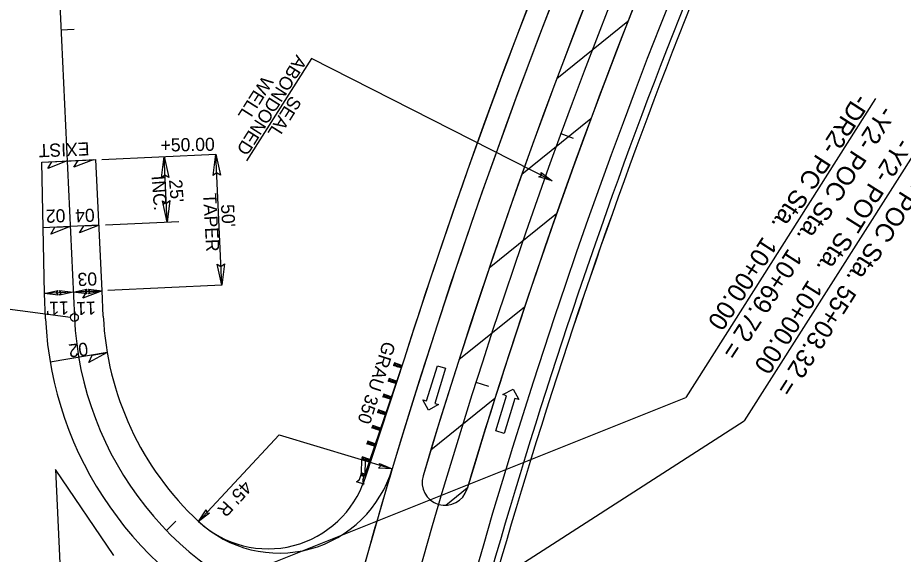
# Model space of a CAD drawing. Extents: x 1778969 to 1790720, y 807089 to 817794.
# Drawn here: x 1780913.9 to 1781249.7, y 812166.6 to 812371.1 of the extents above; entities that cross this region are included whole.
import ezdxf

# ---------------------------------------------------------------- set-up
doc = ezdxf.new("R2010")
doc.units = 0
for name, color, linetype in [('Prop CMT Guardrail Graphics', 7, 'Continuous'), ('Prop Conc Shoulder Berm Gutter', 7, 'Continuous'), ('Prop Dimension', 7, 'Continuous'), ('Prop Dimension Text', 7, 'Continuous'), ('Prop DSN Text', 7, 'Continuous'), ('Prop EOT', 7, 'Continuous'), ('Prop Guardrail', 7, 'Continuous'), ('Prop Guardrail Anchor Unit CELL', 7, 'Continuous'), ('Prop Hatching', 7, 'Continuous'), ('Prop Horizontal Alignment', 7, 'Continuous'), ('Prop Horizontal Alignment Station Label', 7, 'Continuous'), ('Prop Horizontal Alignment Tick Small', 7, 'Continuous'), ('Prop Lane Arrow CELL', 7, 'Continuous'), ('Prop Lane Lines', 7, 'Continuous'), ('Prop Paved Shoulder', 7, 'Continuous'), ('Prop Rem of Exist Asph Pvmt', 7, 'Continuous'), ('Prop Superelevation  Arrow CELL', 7, 'Continuous'), ('Prop Superelevation Label', 7, 'Continuous'), ('Prop Terminator CELL', 7, 'Continuous'), ('Scratch_Level_2', 7, 'Continuous'), ('Scratch_Level_3', 7, 'Continuous'), ('Scratch_Level_7', 7, 'Continuous')]:
    doc.layers.add(name, color=color, linetype=linetype)

msp = doc.modelspace()

# ---------------------------------------------------------------- linework, layer by layer
at = {"layer": 'Prop CMT Guardrail Graphics'}
msp.add_line((1781061.04, 812240.97), (1781045.25, 812192.86), dxfattribs=at)
msp.add_arc((1783308.81, 811525.98), 2358.75, 152.51849, 162.35467, dxfattribs=at)
at = {"layer": 'Prop Conc Shoulder Berm Gutter'}
msp.add_arc((1783308.81, 811525.98), 2303.58, 153.74801, 164.19896, dxfattribs=at)
at = {"layer": 'Prop Dimension'}
for p, q in [((1780945.89, 812317.07), (1780989.3, 812319.1)), ((1780970.82, 812293.21), (1780969.65, 812318.18)), ((1780991.63, 812269.15), (1780989.3, 812319.1)), ((1780947.3, 812292.11), (1780975.24, 812293.42)), ((1780935.02, 812266.51), (1780924.04, 812266)), ((1780946.01, 812267.03), (1780936.2, 812266.57)), ((1780991.63, 812269.15), (1780948.22, 812267.13)), ((1781013.41, 812212.1), (1780982.8, 812179.11)), ((1781013.41, 812212.1), (1781056.53, 812199.21))]:
    msp.add_line(p, q, dxfattribs=at)
at = {"layer": 'Prop DSN Text'}
for p, q in [((1781025.77, 812355.45), (1781001.08, 812316.55)), ((1781117.48, 812308.94), (1781025.77, 812355.45))]:
    msp.add_line(p, q, dxfattribs=at)
at = {"layer": 'Prop EOT'}
for p, q in [((1780923.03, 812316.01), (1780943.69, 812316.97)), ((1780946.01, 812267.03), (1780943.68, 812316.97)), ((1780924.04, 812266), (1780923.03, 812316.01)), ((1780946.46, 812257.37), (1780946.01, 812267.03)), ((1780924.49, 812256.35), (1780924.04, 812266))]:
    msp.add_line(p, q, dxfattribs=at)
for centre, radius, start, end in [((1783308.81, 811525.98), 2350.75, 144.08998, 163.35801), ((1783308.81, 811525.98), 2309.25, 153.74801, 174.52695), ((1781060.34, 812262.68), 114, 182.6702, 227.147), ((1781060.34, 812262.68), 136, 182.6702, 247.3077), ((1781013.41, 812212.1), 45, 227.147, 343.358)]:
    msp.add_arc(centre, radius, start, end, dxfattribs=at)
at = {"layer": 'Prop Guardrail'}
for radius, start, end in [(2358.75, 144.08998, 162.35467), (2301.25, 153.74801, 164.19128)]:
    msp.add_arc((1783308.81, 811525.98), radius, start, end, dxfattribs=at)
at = {"layer": 'Prop Guardrail Anchor Unit CELL'}
for p, q in [((1781061.04, 812240.97), (1781045.97, 812196.71)), ((1781057.38, 812239.53), (1781057.05, 812238.58)), ((1781057.05, 812238.58), (1781058.8, 812239.05)), ((1781059.89, 812237.62), (1781057.05, 812238.58)), ((1781060.22, 812238.56), (1781057.38, 812239.53)), ((1781058.47, 812238.1), (1781057.38, 812239.53)), ((1781058.8, 812239.05), (1781058.47, 812238.1)), ((1781058.47, 812238.1), (1781060.22, 812238.56)), ((1781059.89, 812237.62), (1781058.47, 812238.1)), ((1781058.8, 812239.05), (1781059.89, 812237.62)), ((1781060.22, 812238.56), (1781059.89, 812237.62)), ((1781055.3, 812233.58), (1781054.97, 812232.64)), ((1781054.97, 812232.64), (1781056.74, 812233.09)), ((1781058.19, 812232.6), (1781055.3, 812233.58)), ((1781056.42, 812232.14), (1781055.3, 812233.58)), ((1781056.74, 812233.09), (1781056.42, 812232.14)), ((1781056.74, 812233.09), (1781057.86, 812231.65)), ((1781057.86, 812231.65), (1781054.97, 812232.64)), ((1781058.19, 812232.6), (1781056.42, 812232.14)), ((1781053.27, 812227.62), (1781052.95, 812226.67)), ((1781052.95, 812226.67), (1781054.71, 812227.13)), ((1781055.83, 812225.69), (1781052.95, 812226.67)), ((1781056.15, 812226.63), (1781053.27, 812227.62)), ((1781054.39, 812226.18), (1781053.27, 812227.62)), ((1781054.71, 812227.13), (1781054.39, 812226.18)), ((1781056.15, 812226.63), (1781054.39, 812226.18)), ((1781054.71, 812227.13), (1781055.83, 812225.69)), ((1781051.25, 812221.65), (1781050.93, 812220.7)), ((1781050.93, 812220.7), (1781052.69, 812221.16)), ((1781053.8, 812219.72), (1781050.93, 812220.7)), ((1781054.12, 812220.67), (1781051.25, 812221.65)), ((1781052.36, 812220.21), (1781051.25, 812221.65)), ((1781052.69, 812221.16), (1781052.36, 812220.21)), ((1781054.12, 812220.67), (1781052.36, 812220.21)), ((1781052.69, 812221.16), (1781053.8, 812219.72)), ((1781054.12, 812220.67), (1781053.8, 812219.72)), ((1781049.12, 812215.72), (1781048.8, 812214.77)), ((1781048.8, 812214.77), (1781050.61, 812215.21)), ((1781051.77, 812213.76), (1781048.8, 812214.77)), ((1781052.09, 812214.7), (1781049.12, 812215.72)), ((1781050.29, 812214.26), (1781049.12, 812215.72)), ((1781050.61, 812215.21), (1781050.29, 812214.26)), ((1781052.09, 812214.7), (1781050.29, 812214.26)), ((1781050.61, 812215.21), (1781051.77, 812213.76)), ((1781047.22, 812209.71), (1781046.9, 812208.76)), ((1781050.06, 812208.74), (1781047.22, 812209.71)), ((1781048.32, 812208.28), (1781047.22, 812209.71)), ((1781046.9, 812208.76), (1781048.64, 812209.22)), ((1781049.74, 812207.79), (1781046.9, 812208.76)), ((1781048.64, 812209.22), (1781048.32, 812208.28)), ((1781050.06, 812208.74), (1781048.32, 812208.28)), ((1781048.64, 812209.22), (1781049.74, 812207.79)), ((1781044.81, 812202.81), (1781044.71, 812197.67)), ((1781045.13, 812203.76), (1781044.81, 812202.81)), ((1781044.81, 812202.81), (1781046.58, 812203.27)), ((1781047.71, 812201.83), (1781044.81, 812202.81)), ((1781048.03, 812202.77), (1781045.13, 812203.76)), ((1781046.26, 812202.32), (1781045.13, 812203.76)), ((1781046.58, 812203.27), (1781046.26, 812202.32)), ((1781048.03, 812202.77), (1781046.26, 812202.32)), ((1781046.58, 812203.27), (1781047.71, 812201.83)), ((1781046.26, 812202.32), (1781046.13, 812197.19)), ((1781044.1, 812195.13), (1781044.72, 812197.08)), ((1781044.71, 812197.67), (1781044.39, 812196.72)), ((1781044.39, 812196.72), (1781046.13, 812197.19)), ((1781045.81, 812196.24), (1781044.39, 812196.72)), ((1781044.71, 812197.67), (1781044.55, 812197.2)), ((1781046.13, 812197.19), (1781044.71, 812197.67)), ((1781045.81, 812196.24), (1781044.71, 812197.67)), ((1781044.72, 812197.08), (1781045.3, 812196.9)), ((1781045.89, 812196.71), (1781045.26, 812194.76)), ((1781045.3, 812196.9), (1781045.89, 812196.71)), ((1781042.92, 812194.27), (1781044.1, 812195.13)), ((1781045.72, 812193.38), (1781042.92, 812194.27)), ((1781045.26, 812194.76), (1781045.72, 812193.38))]:
    msp.add_line(p, q, dxfattribs=at)
at = {"layer": 'Prop Hatching'}
for p, q in [((1781146.27, 812369.55), (1781119.18, 812347.72)), ((1781132.19, 812332.52), (1781105.85, 812311.3)), ((1781119.1, 812296.29), (1781093.46, 812275.63)), ((1781106.94, 812260.81), (1781081.93, 812240.66)), ((1781095.63, 812226.01), (1781071.21, 812206.33)), ((1781085.12, 812191.86), (1781076.97, 812185.29))]:
    msp.add_line(p, q, dxfattribs=at)
at = {"layer": 'Prop Horizontal Alignment'}
msp.add_line((1780911.31, 812775.03), (1780935.47, 812256.86), dxfattribs=at)
for centre, radius, start, end in [((1783308.81, 811525.98), 2330, 144.08998, 185.35942), ((1781060.34, 812262.68), 125, 182.6702, 254.314)]:
    msp.add_arc(centre, radius, start, end, dxfattribs=at)
at = {"layer": 'Prop Horizontal Alignment Station Label'}
for p, q in [((1781240.65, 812340.23), (1781168.41, 812226.38)), ((1781257.48, 812322.83), (1781190.63, 812217.49)), ((1780933.98, 812256.79), (1780712.98, 812286.51)), ((1780995.43, 812157.24), (1781168.41, 812226.38)), ((1781060.57, 812133.95), (1781190.63, 812217.49))]:
    msp.add_line(p, q, dxfattribs=at)
msp.add_circle((1780935.47, 812256.86), 1.5, dxfattribs=at)
at = {"layer": 'Prop Horizontal Alignment Tick Small'}
for p, q in [((1780930.37, 812366.4), (1780935.36, 812366.64)), ((1781120.78, 812326.87), (1781125.48, 812325.15)), ((1780935.02, 812266.51), (1780940.02, 812266.75)), ((1781088.43, 812232.26), (1781093.2, 812230.74)), ((1780970.54, 812175.73), (1780974.13, 812179.21))]:
    msp.add_line(p, q, dxfattribs=at)
at = {"layer": 'Prop Lane Arrow CELL'}
for p, q in [((1781069.61, 812225.08), (1781073.71, 812238.47)), ((1781076.86, 812237.51), (1781072.77, 812224.12)), ((1781073.71, 812238.47), (1781076.86, 812237.51)), ((1781098.67, 812227.45), (1781102.56, 812229.56)), ((1781102.56, 812229.56), (1781104.7, 812225.61)), ((1781096.01, 812213.62), (1781100.11, 812227.01)), ((1781100.11, 812227.01), (1781098.67, 812227.45)), ((1781070.31, 812221.58), (1781068.18, 812225.52)), ((1781068.18, 812225.52), (1781069.61, 812225.08)), ((1781074.2, 812223.68), (1781070.31, 812221.58)), ((1781072.77, 812224.12), (1781074.2, 812223.68)), ((1781103.26, 812226.05), (1781099.16, 812212.66)), ((1781104.7, 812225.61), (1781103.26, 812226.05)), ((1781099.16, 812212.66), (1781096.01, 812213.62))]:
    msp.add_line(p, q, dxfattribs=at)
at = {"layer": 'Prop Lane Lines'}
for centre, radius, start, end in [((1783308.81, 811525.98), 2338.75, 144.36073, 163.33829), ((1783308.81, 811525.98), 2321.25, 144.3813, 163.33829), ((1783308.81, 811525.98), 2338.75, 148.12573, 163.33829), ((1783308.81, 811525.98), 2321.25, 148.12573, 163.33829), ((1783308.81, 811525.98), 2321.25, 153.74801, 163.33829), ((1781076.64, 812194.04), 8.75, 163.3383, 343.3383), ((1781076.64, 812194.04), 8.75, 163.3383, 343.3383)]:
    msp.add_arc(centre, radius, start, end, dxfattribs=at)
at = {"layer": 'Prop Paved Shoulder'}
msp.add_line((1781061.04, 812240.97), (1781046.1, 812195.43), dxfattribs=at)
for centre, radius, start, end in [((1783308.81, 811525.98), 2358.75, 144.08998, 162.35467), ((1781009.23, 812207.53), 38.8, 227.0833, 341.8379)]:
    msp.add_arc(centre, radius, start, end, dxfattribs=at)
at = {"layer": 'Prop Rem of Exist Asph Pvmt'}
msp.add_line((1780950.52, 812166.14), (1780928.32, 812198.92), dxfattribs=at)
msp.add_lwpolyline([(1780928.32, 812198.92), (1780930.56, 812149.53), (1780931.1, 812134.79), (1780931.23, 812131.33)], dxfattribs=at)
at = {"layer": 'Prop Superelevation  Arrow CELL'}
for p, q in [((1780923.03, 812316.01), (1780942.68, 812316.92)), ((1780933.86, 812291.49), (1780923.53, 812291)), ((1780944.85, 812292), (1780933.86, 812291.49)), ((1780935.02, 812266.51), (1780946.01, 812267.03)), ((1780947.97, 812243.48), (1780926.28, 812239.77))]:
    msp.add_line(p, q, dxfattribs=at)
for points in [[(1780942.68, 812316.92), (1780935.31, 812314.08), (1780936.91, 812316.66)], [(1780932.69, 812316.46), (1780925.32, 812313.61), (1780926.92, 812316.19)], [(1780933.86, 812291.49), (1780926.48, 812288.64), (1780928.08, 812291.22)], [(1780944.85, 812292), (1780937.47, 812289.15), (1780939.07, 812291.73)], [(1780946.01, 812267.03), (1780938.64, 812264.18), (1780940.24, 812266.76)], [(1780947.97, 812243.48), (1780941, 812239.75), (1780942.27, 812242.5)]]:
    msp.add_lwpolyline(points, close=True, dxfattribs=at)
at = {"layer": 'Prop Terminator CELL'}
for points in [[(1780968.64, 812310.03), (1780969.65, 812318.18), (1780971.47, 812310.11), (1780969.98, 812311.08)], [(1780988.29, 812310.94), (1780989.3, 812319.1), (1780991.12, 812311.03), (1780989.63, 812312)], [(1781113.26, 812312.08), (1781117.48, 812308.94), (1781112.42, 812310.47), (1781113.43, 812310.99)], [(1780971.83, 812301.37), (1780970.82, 812293.21), (1780969, 812301.28), (1780970.49, 812300.31)], [(1780992.65, 812277.31), (1780991.63, 812269.15), (1780989.81, 812277.22), (1780991.3, 812276.26)], [(1780929.26, 812265.35), (1780924.04, 812266), (1780929.2, 812267.16), (1780928.58, 812266.21)], [(1780929.8, 812267.16), (1780935.02, 812266.51), (1780929.86, 812265.35), (1780930.48, 812266.3)], [(1780940.24, 812265.86), (1780935.02, 812266.51), (1780940.19, 812267.68), (1780939.57, 812266.73)], [(1780940.79, 812267.68), (1780946.01, 812267.03), (1780940.85, 812265.86), (1780941.47, 812266.81)], [(1781051.68, 812201.25), (1781056.53, 812199.21), (1781051.24, 812199.49), (1781052.09, 812200.24)], [(1780986.98, 812182.3), (1780982.8, 812179.11), (1780985.67, 812183.56), (1780985.9, 812182.44)]]:
    msp.add_lwpolyline(points, close=True, dxfattribs=at)
at = {"layer": 'Scratch_Level_2'}
msp.add_arc((1783308.81, 811525.98), 2350.75, 163.35801, 165.95604, dxfattribs=at)
at = {"layer": 'Scratch_Level_3'}
msp.add_arc((1783308.81, 811525.98), 2350.75, 144.08998, 164.89021, dxfattribs=at)
at = {"layer": 'Scratch_Level_7'}
msp.add_arc((1783308.81, 811525.98), 2301.26, 153.74801, 164.19128, dxfattribs=at)

# ---------------------------------------------------------------- texts
at = {"layer": 'Prop Dimension Text'}
for s, rotation, p in [('+50.00', 0.9523, (1780968.34, 812320.02)), ('INC.', 274.341, (1780964.81, 812310.71)), ("25'", 274.341, (1780971.5, 812309.26)), ('TAPER', 273.1477, (1780984.5, 812304.03)), ("50'", 273.1477, (1780991.29, 812299.87)), ("11'", 181.4489, (1780933.31, 812263.01)), ("11'", 182.1397, (1780943.58, 812262.98)), ("45' R", 227.1014, (1780999.99, 812195.09))]:
    msp.add_text(s, height=5, rotation=rotation, dxfattribs=at).set_placement(p)
at = {"layer": 'Prop DSN Text'}
for s, p in [('ABONDONED', (1781020.11, 812357.16)), ('WELL', (1781007.32, 812349.24)), ('SEAL', (1781018.04, 812341.67))]:
    msp.add_text(s, height=5, rotation=237.6004, dxfattribs=at).set_placement(p)
at = {"layer": 'Prop Guardrail Anchor Unit CELL'}
msp.add_text('GRAU 350', height=5, rotation=252.1425, dxfattribs=at).set_placement((1781053.16, 812248.11))
at = {"layer": 'Prop Horizontal Alignment Station Label'}
for s, rotation, p in [('-DR2- PC Sta.  10+00.00', 237.0405, (1781233.12, 812342.6)), ('-Y2- POC Sta.  10+69.72 =', 237.0405, (1781242.79, 812338.07)), ('-Y2- POT Sta.  10+00.00', 237.866, (1781249.05, 812325.78)), ('-Y- POC Sta. 55+03.32 =', 237.6004, (1781258.44, 812318.18))]:
    msp.add_text(s, height=7, rotation=rotation, dxfattribs=at).set_placement(p)
at = {"layer": 'Prop Superelevation Label'}
for s, rotation, p in [('EXIST', 182.2463, (1780941.1, 812323.61)), ('02', 182.2463, (1780931.95, 812298.16)), ('04', 182.2463, (1780943.09, 812298.35)), ('03', 182.2463, (1780944.02, 812274.07)), ('02', 186.6484, (1780940.39, 812247.41))]:
    msp.add_text(s, height=5, rotation=rotation, dxfattribs=at).set_placement(p)

doc.saveas('drawing.dxf')
